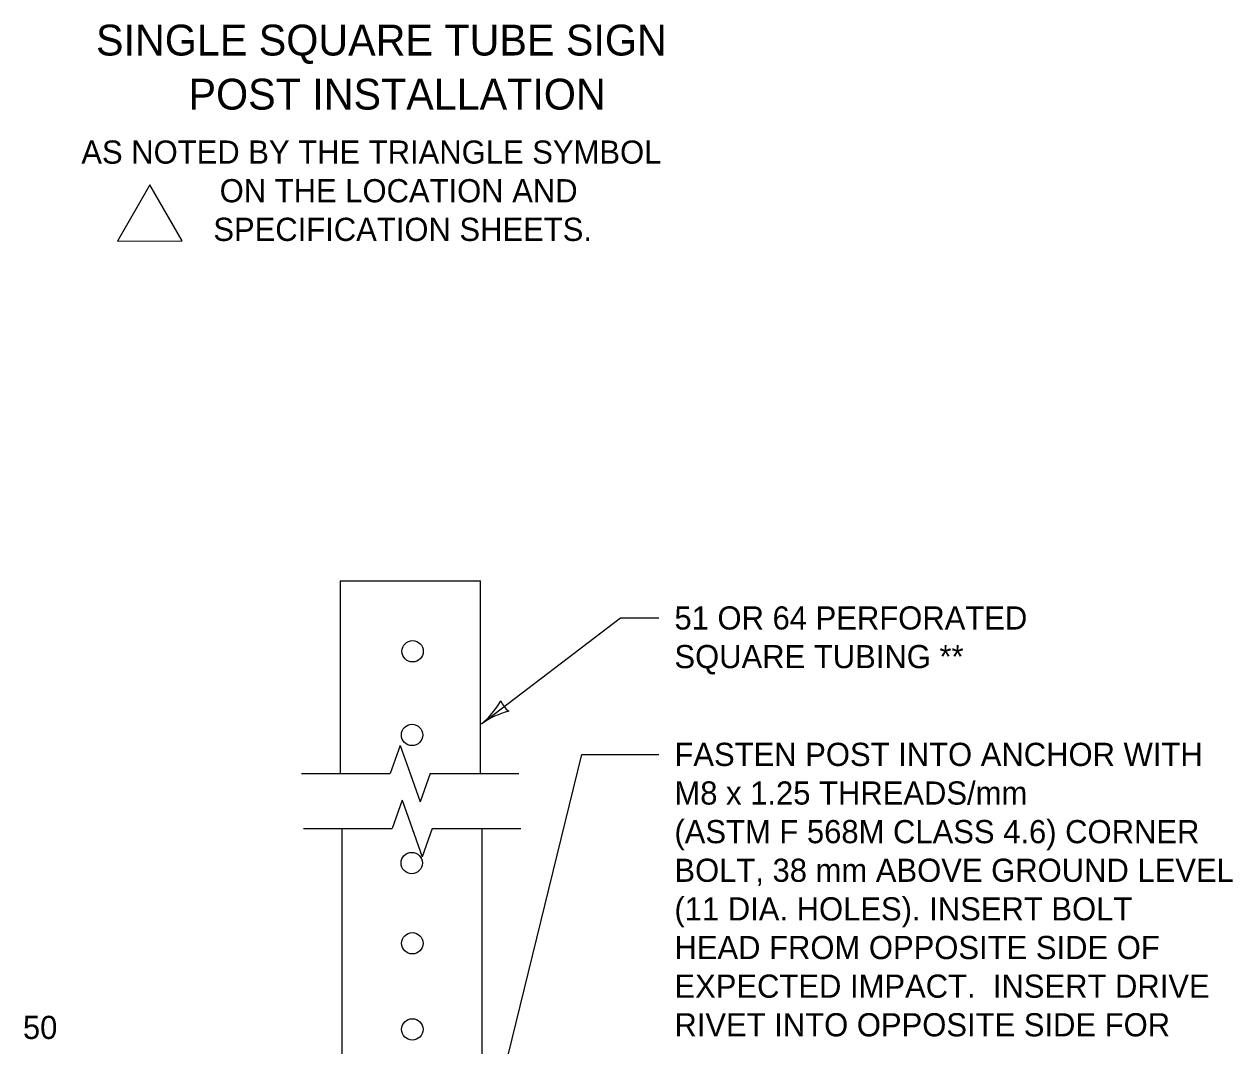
# Model space of a CAD drawing. Extents: x 49940 to 50043, y 49986 to 50011.
# Drawn here: x 50038.725 to 50041.856, y 49993.853 to 49996.498 of the extents above; entities that cross this region are included whole.
import ezdxf

# ---------------------------------------------------------------- set-up
doc = ezdxf.new("R2010")
doc.units = 0
for name, color, linetype in [('Level 1', 7, 'Continuous'), ('Level 2', 7, 'Continuous'), ('Level 3', 7, 'Continuous'), ('Level 6', 7, 'Continuous')]:
    doc.layers.add(name, color=color, linetype=linetype)

msp = doc.modelspace()

# ---------------------------------------------------------------- linework, layer by layer
at = {"layer": 'Level 1'}
msp.add_line((50039.5433, 49995.0566), (50039.9067, 49995.0566), dxfattribs=at)
for points in [[(50039.5433, 49995.0566), (50039.5433, 49994.5576)], [(50039.9067, 49994.5576), (50039.9067, 49995.0566)], [(50039.5482, 49994.4155), (50039.5482, 49993.5309), (50039.9116, 49993.5309), (50039.9114, 49994.4156)]]:
    msp.add_lwpolyline(points, dxfattribs=at)
for centre in [(50039.7312, 49994.8745), (50039.7298, 49994.6578), (50039.729, 49994.3261), (50039.7305, 49994.1185), (50039.7305, 49993.8954)]:
    msp.add_circle(centre, 0.0277, dxfattribs=at)
at = {"layer": 'Level 2'}
msp.add_lwpolyline([(50038.9667, 49995.9361), (50039.1345, 49995.9366), (50039.0501, 49996.0815)], close=True, dxfattribs=at)
at = {"layer": 'Level 3'}
for p, q in [((50039.9098, 49994.6867), (50040.2693, 49994.9607)), ((50040.2693, 49994.9607), (50040.3694, 49994.9607)), ((50039.8897, 49993.4639), (50040.1695, 49994.6075)), ((50040.1695, 49994.6075), (50040.3694, 49994.6075))]:
    msp.add_line(p, q, dxfattribs=at)
for centre, radius, start, end in [((50039.7596, 49994.8648), 0.233, 310.1409, 329.3907), ((50040.0372, 49994.5045), 0.2223, 104.7696, 124.9531), ((50040.0118, 49994.7644), 0.0548, 199.4524, 235.1747)]:
    msp.add_arc(centre, radius, start, end, dxfattribs=at)
at = {"layer": 'Level 6'}
for p, q in [((50039.6991, 49994.6307), (50039.6732, 49994.5576)), ((50039.6991, 49994.6307), (50039.725, 49994.5576)), ((50039.4433, 49994.5576), (50039.6732, 49994.5576)), ((50039.725, 49994.5576), (50039.7509, 49994.4845)), ((50039.7768, 49994.5576), (50039.7509, 49994.4845)), ((50039.7768, 49994.5576), (50040.0067, 49994.5576)), ((50039.7039, 49994.4886), (50039.678, 49994.4155)), ((50039.7039, 49994.4886), (50039.7298, 49994.4155)), ((50039.4483, 49994.4155), (50039.678, 49994.4155)), ((50039.7298, 49994.4155), (50039.7557, 49994.3424)), ((50039.7816, 49994.4155), (50039.7557, 49994.3424)), ((50039.7816, 49994.4156), (50040.0113, 49994.4156))]:
    msp.add_line(p, q, dxfattribs=at)

# ---------------------------------------------------------------- texts
at = {"layer": 'Level 2'}
for s, height, p in [('SINGLE SQUARE TUBE SIGN', 0.0799, (50038.9111, 49996.4167)), ('POST INSTALLATION', 0.0799, (50039.1508, 49996.2767)), ('AS NOTED BY THE TRIANGLE SYMBOL', 0.06, (50038.8731, 49996.1367)), ('ON THE LOCATION AND', 0.06, (50039.2314, 49996.0367)), ('SPECIFICATION SHEETS.', 0.06, (50039.215, 49995.9367)), ('51 OR 64 PERFORATED', 0.06, (50040.4094, 49994.9307)), ('SQUARE TUBING **', 0.06, (50040.4094, 49994.8307)), ('FASTEN POST INTO ANCHOR WITH ', 0.06, (50040.4094, 49994.5775)), ('M8 x 1.25 THREADS/mm', 0.06, (50040.4094, 49994.4775)), ('(ASTM F 568M CLASS 4.6) CORNER', 0.06, (50040.4094, 49994.3775)), ('BOLT, 38 mm ABOVE GROUND LEVEL ', 0.06, (50040.4094, 49994.2775)), ('(11 DIA. HOLES). INSERT BOLT ', 0.06, (50040.4094, 49994.1775)), ('HEAD FROM OPPOSITE SIDE OF ', 0.06, (50040.4094, 49994.0775)), ('EXPECTED IMPACT.  INSERT DRIVE ', 0.06, (50040.4094, 49993.9775)), ('RIVET INTO OPPOSITE SIDE FOR ', 0.06, (50040.4094, 49993.8775)), ('50', 0.06, (50038.7218, 49993.8707))]:
    msp.add_text(s, height=height, dxfattribs=at).set_placement(p)

doc.saveas('drawing.dxf')
